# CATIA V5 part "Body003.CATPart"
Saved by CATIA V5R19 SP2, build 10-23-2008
Part number: Body003
Definition: design
Nomenclature: Body003
Source: Unknown
Bounding box of the stored display mesh (mm): x -43.94 to -39.44, y -7 to 0, z 15.25 to 25.25
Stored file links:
  Z:\fausse table rondelle-20220905T211342Z-001\fausse table rondelle\Body003.CATPart
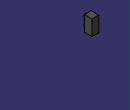
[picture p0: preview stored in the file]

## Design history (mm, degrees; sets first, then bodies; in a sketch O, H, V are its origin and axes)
AxisSystem1: origin (0, 0, 0), X (1, 0, 0), Y (0, 1, 0), Z (0, 0, 1)
Body1 "MANIFOLD_SOLID_BREP #239287" (main body)
  Solid1: solid without history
